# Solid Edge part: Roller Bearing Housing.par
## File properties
Title: Roller Bearing Housing
Author: Dan
Template: Normal.par
Last saved by: Dan
Revision: 66
Application: Solid Edge
Density: 0 kg/mm^3
Accuracy: 0.99
Document Number: P52-004-1
Project Name: Piston Pump P52
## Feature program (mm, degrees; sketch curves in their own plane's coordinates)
sketch for "unnamed RevolvedProtrusion 1" plane through (0, 0, 0) normal (0, -1, 0) x-axis (1, 0, 0)
  line (46.3, 0) -> (46.3, 3.3)
  line (40.3386, 15) -> (46.3, 3.3)
  line (22, 15) -> (40.3386, 15)
  line (22, 11.8) -> (22, 15)
  line (22, 11.8) -> (26.2, 11.8)
  arc centre (26.2, 11.2) radius 0.6 from (26.2, 11.8) to (26.4, 10.6343) cw
  line (26.4, 4.3657) -> (26.4, 10.6343)
  arc centre (26.2, 3.8) radius 0.6 from (26.2, 3.2) to (26.4, 4.3657) ccw
  line (26.2, 3.2) -> (22, 3.2)
  line (22, 3.2) -> (22, 0)
  line (22, 0) -> (46.3, 0)
  dimension (linear) = 22
  dimension (linear) = 40.3386
  dimension (linear) = 22
revolve "unnamed RevolvedProtrusion 1" add full turn 360 deg
fillet "unnamed Round 1"
chamfer "Chamfer_1" setback 0.5
sketch for "unnamed RevolvedCutout 1" plane through (0, 0, 0) normal (0, -1, 0) x-axis (1, 0, 0)
  line (-20.3598, 14.7) -> (-40.7957, 14.7)
  line (-20.3598, 11.4) -> (-20.3598, 14.7)
  line (-26.5, 11.4) -> (-20.3598, 11.4)
  line (-26.5, 3.6) -> (-26.5, 11.4)
  line (-26.5, 3.6) -> (-20.075, 3.6)
  line (-20.075, 3.6) -> (-20.075, 0.3)
  line (-20.075, 0.3) -> (-45.3, 0.3)
  dimension (linear) = 26.5
revolve "unnamed RevolvedCutout 1" cut full turn 360 deg
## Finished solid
Body 1: solid body, 17 faces, 17 edges, 0 vertices.
  Faces by surface: torus 6, cylinder 4, plane 4, cone 3
  Edges by curve: circle 17
Bounding box of the edges (mm; curved faces can reach further): 92.600 x 92.600 x 15.000, from (-46.3, -46.3, 0) to (46.3, 46.3, 15).
Cylindrical faces by radius (mm): R22 x2, R26.4 x1, R46.3 x1
Conical faces (half-angle, radius in mm at the cone's reference point): 27 deg R46.3 x1, 45 deg R22 x1, 45 deg R22.5 x1
Toroidal faces (ring radius, tube radius in mm): R23 r1 x2, R26.2 r0.6 x2, R39.7258 r1 x1, R45.3 r1 x1
Planar faces by outward normal: +z 2, -z 2
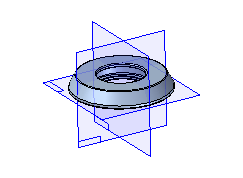
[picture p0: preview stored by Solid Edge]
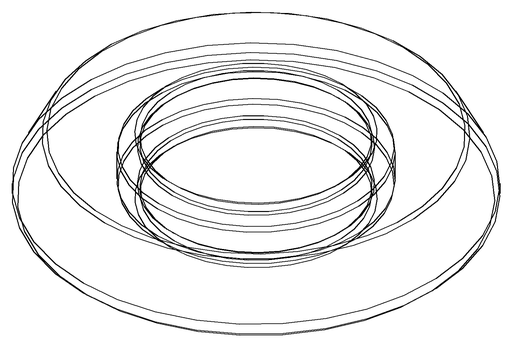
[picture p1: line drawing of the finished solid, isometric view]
